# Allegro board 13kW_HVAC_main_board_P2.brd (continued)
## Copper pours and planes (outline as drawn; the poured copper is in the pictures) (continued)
DRV_W_H on BOTTOM: 111.53,22.58 111.4,22.35 111.17,22.3 110.82,22.48 110.79,22.86 111.96,25.22 112.44,25.32 113.02,26.67 112.95,26.92 111.93,28.52 108.32,30.22 105.04,31.64 105.02,31.75 105.37,32.51 105.5,32.54 107.1,31.8 108.3,31.21 108.56,31.24 110.2,30.46 110.73,30.76 111.01,30.86 111.03,30.85 113.69,29.61 115.05,29.28 115.11,29.11 115.25,28.32 113.43,24.63 113.15,24.58 112.28,24.25 112.15,23.85
G_L on TOP: 111.72,85.75 112.99,85.97 114.26,85.47 114.39,85.21 114.01,84.45 113.88,84.45 112.87,84.96 112.61,84.96 112.11,83.94 111.98,83.94 111.34,84.2 111.19,84.58
G_L on BOTTOM: 51.78,82.93 51.4,83.31 51.4,84.45 51.65,84.7 53.56,84.7 53.69,84.58 53.69,83.05 53.56,82.93
G_L on BOTTOM: 70.96,37.84 70.96,37.33 71.21,36.95 71.47,36.95 72.1,37.33 72.23,37.59 71.97,38.1 71.72,38.22
G_L on BOTTOM: 102.96,82.16 102.2,82.55 102.07,82.93 102.45,83.82 102.83,84.45 103.09,84.45 103.85,84.07 103.85,83.82 103.22,82.29
G_L on I_SAMPLING05: 53.18,92.71 56.35,92.71 56.61,92.32 56.61,82.8 56.39,82.52 51.97,82.54 51.97,82.55 51.57,82.55 51.22,82.9 51.22,84.65 50.79,85.09 46.32,85.09 45.79,85.68 45.3,88.01 45.3,98.17 45.56,98.55 46.19,98.54 49.85,98.53 50.76,97.53 50.76,92.96 51.16,92.72
G_L on I_SAMPLING05: 100.68,81.28 102.06,84.21 105.81,87.96 107.16,88.39 118.98,83.34 119.19,82.31 118.36,80.43 116.02,79.32 112.41,80.86 111.29,80.46 109.26,76.22 109.08,76.2 108.73,76.17 107.16,76.84 100.39,79.94 100.4,80.72
G_L on I_SAMPLING05: 60.93,31.89 62.21,34.42 60.92,37.46 61.43,38.48 69.9,42.44 69.94,42.41 70.32,42.29 72.35,37.97 71.31,35.92 72.55,33.1 72.44,31.89 63.75,27.68 63.06,26.41 61.66,25.73 61.25,25.9 59.58,29.54 59.63,29.66
G_U_H on I_SAMPLING05: 96.1,111.38 96.1,107.08 96.08,107.06 96.08,106.68 96.7,106.05 101.75,106.05 102.1,105.71 102.1,103.86 102.66,103.3 107,103.3 107,105.96 106.97,105.99 106.97,107.13 108.85,109.01 108.85,112.8 107.3,114.35 104.76,114.35 103.9,113.48 99.23,113.48 98.67,114.04 96.31,114.04 96.31,114.02 96.1,113.81
G_V_H on I_SAMPLING05: 32.66,75.76 30.2,74.65 29.96,73.84 31.94,69.11 31.94,68.25 31.08,67.94 30.32,67.56 27.14,66.04 25.36,65.27 24.86,65.27 24.17,66.44 22.77,69.36 22.47,69.44 22.45,69.44 21.91,70.59 20.61,70.51 20.36,71.04 20.36,72.27 19.47,74.29 19.46,74.84 28.3,79 28.97,79.02 29.5,79.02 31.28,79.78 31.71,79.57 32.65,77.44 33.37,77.34 33.67,76.58 33.57,76.12
G_W_H on I_SAMPLING05: 106.16,33.71 108.77,32.52 109.03,32.39 109.45,32.57 109.54,32.61 113.22,30.96 115.15,26.36 113.18,21.92 110.12,21.26 106.87,22.68 106.72,23.69 103.85,25.04 103.7,25.95 104.69,28.09 103.09,31.67 103.19,31.97 104.03,33.8 105.02,34.03 106.16,33.71
IPH_U- on TOP: 66.66,63.16 66.65,77.2 60.54,83.31 60.54,86.48 61.05,86.99 63.85,86.99 67.91,82.93 74.77,82.93 75.15,82.55 75.15,79.37 74.74,78.96 74.74,77.95 74.76,47.24 74.76,46.54 73.02,44.8 73.02,37.21 78.96,31.27 78.96,31.21 80.65,27.31 80.65,19.93 73.72,9.73 69.6,6.6 44.8,6.6 44.16,7.23 44.16,16.38 44.92,17.14 66.13,17.14 70.96,21.97 70.96,24.88 69.43,28.06 67.53,31.11 65.55,35.82 65.62,42.97 63.69,46.3 63.52,47.85 63.58,48.13 62.07,57.53 62.07,57.91 62.32,58.29 63.97,59.69 66.13,61.21
IPH_U- on TOP: 92.29,63.75 89.12,65.27 89.12,66.18 93.31,74.8 96.36,75.94 96.87,76.2 101.82,73.91 101.95,72.89 101.06,70.99 95.64,68.96 95.63,68.94 93.18,63.75 92.8,63.5
IPH_U- on BOTTOM: 60.54,83.82 65.12,79.24 79.97,79.24 80.1,79.37 80.1,90.55 79.97,90.67 77.82,90.67 77.31,90.17 77.31,82.93 76.98,82.6 75.55,82.6 75.38,82.77 67.3,82.77 65.24,84.83 65.24,85.59 63.85,86.99 61.05,86.99 60.54,86.48
IPH_U- on BOTTOM: 52.67,59.05 52.67,59.24 54.19,59.94 62.84,63.96 62.86,63.94 64.1,64.38 64.61,64.26 71.34,49.65 70.58,47.24 66.28,45.33 65.24,45.28 64.5,45.48 63.92,45.91 63.59,46.48 63.46,47.11 63.46,47.62 64.86,51.56 61.81,58.16 61.56,58.9 60.47,59.79 59.55,59.68 59.53,59.69 53.69,57.27 53.3,57.4
IPH_U- on BOTTOM: 66.08,3.84 65.75,3.5 56.95,3.5 53.94,6.51 45.4,6.51 43.97,7.94 43.97,16.28 44.57,16.87 51.91,16.87 51.95,16.83 53.05,16.83 54.39,15.49 65.57,15.49 66.08,14.98
IPH_U- on BOTTOM: 96.93,69.46 100.9,70.75 101.31,71.06 101.73,71.54 101.99,72.15 101.97,72.87 101.68,73.58 101,74.38 99.3,75.3 96.62,76.37 95.2,76.37 92.97,74.15 92.95,74.1 89.96,67.55 89.66,66.9 89.45,66.41 88.73,64.53 86.93,60.65 87.04,60.13 87.04,60.12 87.22,59.31 96.76,54.86 97.68,54.71 97.81,54.81 97.82,54.82 98.64,56.36 98.59,56.77 98.34,57.15 92.34,60.09 92.34,60.1 91.56,61.08 91.56,61.62 95.49,69.19
IPH_U- on VCC02: 92.29,63.75 89.12,65.27 89.12,66.18 91.84,71.78 96.47,76 96.87,76.2 101.82,73.91 101.95,72.89 101.06,70.99 95.64,68.96 95.63,68.94 93.18,63.75 92.8,63.5
IPH_U- on VCC02: 60.29,86.61 60.29,81.91 61.05,81.15 74.89,81.15 75.28,81.53 75.28,84.07 75.02,84.32 67.15,84.32 64.48,86.99 60.67,86.99
IPH_U- on VCC02: 65.85,44.37 65.19,44.52 63.34,47.98 64.28,51.05 61.46,57.32 61.74,57.86 64,58.92 64.4,58.77 67.6,51.58 69.87,46.78 69.59,46.12
IPH_U- on GND03: 92.29,63.75 89.81,64.94 89.48,66.93 93.31,74.8 96.36,75.94 96.87,76.2 101.82,73.91 101.95,72.89 101.06,70.99 95.64,68.96 95.63,68.94 93.18,63.75 92.8,63.5
IPH_U- on GND03: 65.85,44.37 65.19,44.52 63.34,47.98 64.28,51.05 61.46,57.32 61.74,57.86 63.72,58.79 64.1,58.67 69.75,46.51 69.59,46.12
IPH_U- on GND03: 67.27,82.42 67.27,81.4 67.53,81.15 75.15,81.15 75.4,81.4 75.4,82.29 75.02,82.67 67.53,82.67
IPH_U- on PWM04: 78.73,78.53 79.94,78.53 98.06,75.65 101.21,74.32 101.82,73.15 101.77,72.21 101.08,70.96 98.16,70.38 97.49,70.32 90.13,62.23 86.83,61.08 66.47,45.43 65.18,45.35 64.15,45.84 63.61,46.77 63.59,47.5 63.77,48.18 63.65,53.84 61.94,57.4 63.45,63.62 63.39,66.48 63.29,67.13 60.69,84.4 60.8,85.9 61.36,86.58 62.04,86.89 64.32,86.89 68.5,82.72 69.45,82.72 69.51,82.69 74.88,82.69 75.28,82.29 75.28,81.42 78.47,78.65
IPH_U- on I_SAMPLING05: 42.83,6.41 41.67,7.56 41.67,16.2 42.75,17.28 50.18,17.28 51.89,15.57 63.52,15.57 71.26,23.31 73.4,32.1 73.34,39.47 70.78,43.56 64.63,45.51 64.07,45.94 63.24,47.72 63.36,48.81 62.61,56.01 61.94,57.91 62.18,60.21 60.27,78.58 60.18,83.87 60.64,86.37 62.09,86.99 63.39,86.97 66,85.09 70.49,83.65 83.51,80.6 97.11,77.52 100.84,75.75 101.44,74.9 101.72,73.86 101.79,72.13 101.33,71.33 100.27,70.72 96.99,70.71 87.89,58.82 81.52,48.07 81.51,46.79 81.55,46.68 81.55,19.63 75.58,13.66 75.58,8.07 73.8,5.91 44.04,5.91
NETC7_1 on TOP: 84.04,94.1 84.79,94.62 100.85,94.64 101.24,94.22 104.29,94.23 104.61,93.98 104.61,92.07 104.4,91.86 103.42,91.84 93.92,82.16 84.29,82.16 84.04,82.42
NETC7_1 on TOP: 45.1,79.84 45.35,79.43 47.01,76.16 51.8,73.74 53.46,74.51 56.2,72.88 57.41,70.13 57.24,68.32 47.84,63.37 47.44,63.37 41.33,76.63 40.76,76.92 40.26,78.22 40.32,78.53 40.36,78.73 43.91,80.38
NETC7_1 on TOP: 84.99,45.78 84.29,45.08 83.02,42.41 82.9,42.41 80.99,43.3 80.86,43.43 81.24,44.32 79.97,47.24 79.21,47.24 78.83,47.62 78.82,47.62 78.82,47.75 78.82,48.13 78.7,77.72 79.21,78.35 82.51,78.35 83.78,77.08 83.78,62.57 83.81,62.52 85.56,56.89 90.64,54.48 98.39,50.16 98.55,48.74 98.38,48.39 98.39,48.38 96.1,43.56 95.92,43.21 95.62,43.13 92.36,44.64 90.17,45.71 87.35,45.71 87.28,45.78
NETC7_1 on BOTTOM: 70.58,3.04 70.07,3.55 70.07,15.62 74.39,19.93 77.55,29.53 77.82,30.09 77.84,32.01 78.9,37.15 81.54,46.97 85.62,55.97 85.94,55.97 85.94,55.98 98.54,50.21 98.75,49.77 90.57,32.58 89.09,31.04 89.02,21.35 89.03,21.34 89.03,17.63 92.86,13.8 92.86,4.92 91.71,3.76 88.92,3.76 88.2,3.04
NETC7_1 on BOTTOM: 84.42,94.48 100.8,94.48 101.19,94.33 101.31,94.23 101.31,91.94 100.56,91.07 99.1,91.14 86.77,78.81 84.22,78.81 84.17,78.86 84.17,94.23
NETC7_1 on BOTTOM: 60.36,68.43 60.82,67.52 51.53,63.24 49.58,62.27 48.1,62.61 47.84,62.84 46.95,64.77 40.48,78.61 44.16,80.39 44.54,80.13 45.94,77.47 54.07,74.04 55.31,73.35
NETC7_1 on VCC02: 70.7,2.92 70.07,3.55 70.07,17.65 74.39,21.97 74.46,35.43 77.69,38.65 77.69,44.57 70.36,51.9 67.15,59.05 66.26,60.83 66.25,60.83 63.59,66.29 61.18,67.56 50.26,62.35 47.55,62.84 47.53,62.88 47.53,62.88 40.64,77.66 41,78.66 42.09,79.17 43.99,80.06 44.18,80.14 47.65,78.76 48.4,78.49 50.74,73.48 50.87,73.37 64.23,78.74 75.91,78.74 78.7,81.53 78.7,89.92 83.5,94.71 101.21,94.71 101.74,94.18 101.74,90.98 99.79,89.02 99.79,82.93 97.82,80.96 96.48,80.92 95.27,79.4 95.34,78.48 87.98,71.12 84.04,61.97 85.31,58.54 86.32,56.64 91.79,54.1 98.26,50.8 98.79,50.27 92.42,36.73 91.91,35.68 91.91,14.43 92.93,13.42 92.93,4.82 91.98,3.87 88.12,2.92
NETC7_1 on GND03: 92.29,37.59 92.03,37.73 72.57,47.09 71.9,48.29 65.88,60.96 64.85,60.98 60.04,61.27 55.38,59.08 49.72,61.11 48.17,61.57 47.53,62.88 47.53,62.88 40.64,77.66 41,78.66 42.09,79.17 43.99,80.06 44.18,80.14 44.88,79.86 44.88,79.85 46.24,76.99 49.3,76.57 50.6,73.78 52.64,73.78 54.39,74.34 54.66,74.47 54.7,74.44 57.22,75.25 57.37,75.3 65.12,78.8 75.91,78.8 78.7,81.59 78.7,89.94 78.73,89.94 83.48,94.69 101.3,94.69 101.77,94.21 101.74,94.18 101.74,90.37 98.21,86.84 89.8,78.46 85.77,69.97 85.87,67 87.42,61.84 87.98,61.65 90.64,60.38 98.45,56.75 99.84,52.55 93.04,38.1 92.93,37.84
NETC7_1 on PWM04: 42.09,79.17 43.99,80.06 44.18,80.14 44.88,79.86 44.88,79.85 46.24,76.99 49.3,76.57 50.81,73.33 50.91,73.3 51.87,73.17 54.66,74.47 56.01,73.68 59.26,66.74 59.02,66.42 50.13,62.35 49.1,62.31 47.53,62.88 47.53,62.88 40.64,77.66 41,78.66
NETC7_1 on PWM04: 101.61,92.99 101.61,90.89 101.6,90.68 98.89,88.12 98.32,87.55 92.63,87.55 92.56,87.47 92.04,86.66 92.04,83.58 92.04,81.98 91.3,81.25 81.93,81.25 81.12,82.06 81.12,83.94 81.09,91.72 83.19,93.57 84.55,94.93 84.55,94.94 100.85,94.94 101.61,94.19
NETC7_1 on I_SAMPLING05: 42.09,79.17 43.99,80.06 44.18,80.14 47.65,78.76 48.4,78.49 50.81,73.33 50.91,73.3 51.87,73.17 53.69,74.02 54.45,73.91 57.07,68.75 57.09,66.87 48.35,62.86 47.33,63.31 40.64,77.66 41,78.66
NETC7_1 on I_SAMPLING05: 101.61,92.99 101.61,90.89 101.6,90.68 98.89,88.12 98.32,87.55 92.63,87.55 92.56,87.47 92.04,86.66 92.04,83.58 90.75,82.69 83.67,82.68 81.12,83.99 81.09,91.72 83.19,93.57 84.55,94.93 84.55,94.94 100.85,94.94 101.61,94.19
NETC19_1 on BOTTOM (solid shape): 25.1,49.61 26.69,46.2 26.56,45.86 24.61,44.95 24.27,45.07 23.84,46 23.5,46.12 22.83,46.24 20.76,45.27 20.59,45.33 20.27,46.02 20.33,46.19 21.14,46.57 21.38,47.23 21.43,47.25 21,48.18 20.96,48.15 20.8,48.5 20.84,48.52 20.41,49.44 20.37,49.42 20.21,49.77 20.25,49.79 19.96,50.42 20.06,50.69 20.97,51.11
NETC20_1 on BOTTOM: 79.98,124.25 79.98,126.54 80.11,126.66 80.87,126.66 81,126.54 81,125.65 81.51,125.14 84.94,125.14 85.19,124.89 85.19,123.88 82.08,120.77 78.32,120.77 78.07,121.03 78.07,123.19 78.32,123.44 79.34,123.44 79.59,123.69
NETC32_1 on BOTTOM (solid shape): 127.64,43.37 127.77,43.03 127.34,42.11 127.46,41.78 127.8,41.19 128.95,40.65 128.93,40.61 129.89,40.16 129.93,40.05 129.61,39.37 129.46,39.31 129.44,39.3 129.03,39.49 128.23,39.49 127.22,37.46 126.76,37.23 126.58,37.32 124.3,41.9 125.35,44.16 125.69,44.28
NETC60_2 on TOP: 123.92,104.14 128.36,106.17 128.74,105.41 124.3,103.37
NETC65_1 on TOP: 118.48,110.17 118.46,109.98 118.46,109.85 118.71,109.34 118.71,109.35 119.01,109.49 119.02,109.56 118.9,109.84 118.99,110.86 118.85,111.15 118.61,111.64 118.41,112.02 118.35,112.04 117.71,111.75 117.92,111.32 118.27,110.58
NETCON3_1 on TOP, BOTTOM: 48.19,29.3 47.79,28.22 40.72,24.92 39.7,25.29 36.06,33.11 38.02,38.5 36.74,41.23 36.73,41.24 36.52,41.68 36.56,41.78 38.7,42.78 38.71,42.81 38.6,43.04 36.51,42.06 36.31,42.14 34.5,46.01 34.55,46.17 37.59,47.61 38,47.54 39.48,46.03 42.04,40.55 43.11,40.16 44.65,36.86 44.66,36.85 47.74,30.24 47.75,30.23
NETCON3_1 on VCC02: 48.22,29.29 47.82,28.21 43.87,26.36 40.1,26.36 38.47,27.99 36.09,33.09 38.05,38.48 36.78,41.22 36.76,41.22 36.55,41.66 36.59,41.76 38.73,42.76 38.74,42.8 38.64,43.03 36.54,42.05 36.34,42.12 34.54,45.99 34.6,46.22 37.78,47.68 38.63,48.07 39.62,47.71 40.16,46.55 40.16,46.54 44.68,36.84 44.69,36.84 47.77,30.22 47.78,30.22
NETCON3_1 on GND03: 48.23,29.29 47.84,28.21 40.76,24.91 39.75,25.28 36.1,33.1 38.06,38.49 36.79,41.22 36.77,41.23 36.57,41.67 36.6,41.77 38.74,42.77 38.76,42.8 38.65,43.03 36.55,42.05 36.35,42.13 34.55,45.99 34.61,46.22 37.8,47.68 38.65,48.08 39.63,47.72 40.18,46.55 40.17,46.54 44.69,36.85 44.7,36.84 47.79,30.22 47.8,30.22
NETCON3_1 on PWM04: 48.21,29.29 47.81,28.21 40.74,24.91 39.72,25.28 36.08,33.1 38.04,38.49 36.76,41.22 36.75,41.23 36.54,41.67 36.58,41.77 38.72,42.77 38.73,42.8 38.62,43.03 36.53,42.05 36.33,42.13 34.52,45.99 34.59,46.22 37.77,47.68 38.62,48.08 39.6,47.72 40.15,46.55 40.15,46.54 44.67,36.85 44.68,36.84 47.76,30.22 47.77,30.22
NETCON3_1 on I_SAMPLING05: 48.21,29.32 47.81,28.24 40.74,24.94 39.72,25.31 36.08,33.12 38.04,38.51 36.76,41.25 36.75,41.25 36.54,41.69 36.58,41.79 38.72,42.79 38.73,42.82 38.62,43.05 36.53,42.08 36.33,42.15 34.52,46.02 34.59,46.24 37.77,47.7 38.62,48.1 39.6,47.74 40.15,46.57 40.15,46.57 44.67,36.87 44.68,36.87 47.76,30.25 47.77,30.24
NETCON4_1 on TOP, BOTTOM: 124.44,71.53 125.52,71.93 132.6,68.63 132.97,67.61 129.32,59.8 123.93,57.83 122.66,55.1 122.66,55.08 122.46,54.64 122.36,54.61 120.22,55.6 120.18,55.59 120.08,55.36 122.17,54.39 122.24,54.18 120.44,50.32 120.29,50.25 117.22,51.65 117.02,52.01 117.22,54.11 119.78,59.59 119.39,60.67 120.93,63.97 120.93,63.98 124.01,70.59 124.01,70.6
NETCON4_1 on VCC02: 124.44,71.51 125.52,71.9 132.6,68.6 132.97,67.59 129.32,59.77 123.93,57.81 122.66,55.08 122.66,55.06 122.46,54.62 122.36,54.58 120.22,55.58 120.18,55.57 120.08,55.34 122.17,54.36 122.24,54.16 120.44,50.29 120.23,50.19 117.06,51.7 116.21,52.09 115.85,53.07 116.4,54.24 116.41,54.25 120.93,63.94 120.93,63.95 124.01,70.57 124.01,70.58
NETCON4_1 on GND03: 124.46,71.48 125.54,71.88 132.61,68.58 132.98,67.56 129.34,59.75 123.95,57.79 122.67,55.05 122.68,55.03 122.47,54.59 122.37,54.56 120.23,55.56 120.2,55.54 120.09,55.31 122.19,54.34 122.26,54.13 120.46,50.27 120.24,50.17 117.08,51.67 116.23,52.07 115.87,53.05 116.41,54.22 116.42,54.22 117.36,56.24 120.94,63.92 120.94,63.93 124.03,70.55 124.02,70.56
NETCON4_1 on PWM04: 124.45,71.49 125.53,71.89 132.6,68.59 132.97,67.57 129.33,59.75 123.94,57.79 122.67,55.06 122.67,55.04 122.47,54.6 122.37,54.57 120.23,55.56 120.19,55.55 120.08,55.32 122.18,54.35 122.25,54.14 120.45,50.28 120.24,50.18 117.07,51.68 116.22,52.08 115.86,53.06 116.41,54.23 116.42,54.23 117.36,56.25 120.94,63.92 120.94,63.94 124.02,70.55 124.02,70.56
NETCON4_1 on I_SAMPLING05: 124.45,71.52 125.53,71.92 132.61,68.62 132.98,67.6 129.33,59.79 123.95,57.82 122.67,55.09 122.68,55.07 122.47,54.63 122.37,54.6 120.23,55.6 120.2,55.58 120.09,55.35 122.18,54.38 122.26,54.17 120.45,50.31 120.24,50.21 117.07,51.71 116.22,52.11 115.87,53.09 116.41,54.26 116.42,54.26 117.36,56.28 120.94,63.96 120.94,63.97 124.02,70.59 124.02,70.6
NETCON5_1 on TOP: 74.84,113.91 74.97,113.8 74.99,110.43 74.75,110.1 72.76,109.39 66.72,109.39 65.91,108.59 62.27,108.59 62.26,108.58 54.96,108.58 54.95,108.57 53.92,108.57 53.11,109.39 53.11,116.33 53.79,117.01 54.19,117.19 54.96,117.19 55.45,116.95 55.56,116.84 60.95,116.84 61.31,117.19 62.19,117.19 62.43,117.07 62.93,116.58 63.08,116.45 63.08,113.79 64.35,112.52 65.37,112.52 65.37,112.58 68.23,112.6 69.02,112.6 69.2,112.78 69.2,113.59 69.52,113.92 69.58,113.92 69.59,113.91 70.07,113.91 70.14,113.84 70.14,111.48 70.17,111.45 70.42,111.45 70.42,113.76 70.58,113.91
NETCON5_1 on BOTTOM: 53.92,108.57 53.11,109.39 53.11,117.19 53.88,117.96 62.5,117.96 66.55,113.9 69.57,113.9 69.59,113.91 70.07,113.91 70.14,113.84 70.14,111.48 70.17,111.45 70.42,111.45 70.42,113.76 70.58,113.91 74.84,113.91 74.97,113.8 74.99,110.43 74.75,110.1 72.76,109.39 66.72,109.39 65.91,108.59 62.27,108.59 62.26,108.58 54.96,108.58 54.95,108.57
NETCON5_1 on VCC02: 53.95,108.4 53.13,109.22 53.13,117.02 53.9,117.79 62.52,117.79 66.58,113.73 69.59,113.73 69.61,113.74 70.09,113.74 70.17,113.67 70.17,111.31 70.19,111.28 70.45,111.28 70.45,113.59 70.6,113.74 74.87,113.74 75.05,113.59 75.02,110.09 75.02,109.15 74.28,108.41 72.99,108.41 72.99,108.42 62.29,108.42 62.28,108.41 54.98,108.41 54.97,108.4
NETCON5_1 on GND03: 53.93,108.42 53.12,109.24 53.12,115.77 55.15,117.81 62.51,117.81 66.56,113.75 69.58,113.75 69.6,113.77 70.08,113.77 70.15,113.69 70.15,111.33 70.18,111.3 70.43,111.3 70.43,113.61 70.59,113.77 74.85,113.77 75.03,113.61 75.01,110.11 75.01,109.17 74.27,108.43 72.98,108.43 72.97,108.44 62.28,108.44 62.27,108.43 54.96,108.43 54.96,108.42
NETCON5_1 on PWM04: 53.91,108.42 53.09,109.24 53.09,117.04 53.86,117.81 62.48,117.81 66.54,113.75 69.55,113.75 69.57,113.77 70.05,113.77 70.13,113.69 70.13,111.33 70.15,111.3 70.41,111.3 70.41,113.61 70.56,113.77 74.83,113.77 75.01,113.61 74.98,110.11 74.98,109.17 74.24,108.43 72.95,108.43 72.95,108.44 62.25,108.44 62.24,108.43 54.94,108.43 54.93,108.42
NETCON5_1 on I_SAMPLING05: 53.9,108.5 53.09,109.31 53.09,116.33 54.4,117.64 62.71,117.64 66.53,113.83 69.55,113.83 69.56,113.84 70.04,113.84 70.12,113.76 70.12,111.4 70.14,111.37 70.4,111.37 70.4,113.69 70.55,113.84 74.82,113.84 75,113.69 74.97,110.18 74.97,109.24 74.23,108.5 72.94,108.5 72.94,108.51 62.24,108.51 62.23,108.5 54.93,108.5 54.92,108.5
NETPAD8_1 on TOP: 54.01,28.81 53.89,28.48 50.32,26.81 49.98,26.94 43.5,40.84 42.47,41.21 40.08,46.31 38.36,48.15 37.61,48.29 37.43,48.21 34.32,46.76 34.15,46.82 32.37,50.64 32.43,50.81 34.36,51.71 34.41,51.62 34.64,51.73 28.2,65.54 32.99,67.71 33.42,67.56 39.76,53.98 40.49,50.37 42.38,47.92 44.87,46.67 45.77,46.49
NETPAD8_1 on BOTTOM: 54.01,28.81 53.89,28.48 50.32,26.81 49.98,26.94 43.5,40.84 42.47,41.21 40.08,46.31 38.36,48.15 37.61,48.29 37.43,48.21 34.32,46.76 34.15,46.82 32.37,50.64 32.43,50.81 34.36,51.71 34.41,51.62 34.64,51.73 28.2,65.54 28.38,66.05 32.41,67.93 33.42,67.56 39.76,53.98 40.49,50.37 42.38,47.92 44.87,46.67 45.77,46.49
NETPAD8_1 on VCC02: 54.02,28.79 53.9,28.45 50.33,26.79 49.99,26.91 43.37,41.11 43.35,41.12 42.67,42.57 42.68,42.59 39.98,48.39 38.79,48.82 34.33,46.73 34.16,46.8 32.38,50.62 32.44,50.79 34.37,51.69 34.42,51.6 34.65,51.7 28.21,65.51 28.39,66.02 32.42,67.9 33.43,67.53 38.3,57.08 39.15,55.26 42.19,54.16 45.43,47.2
NETPAD8_1 on GND03: 54.03,28.79 53.91,28.45 50.34,26.79 50,26.91 43.38,41.12 43.36,41.12 42.69,42.57 42.69,42.59 39.99,48.39 38.81,48.82 34.34,46.74 34.17,46.8 32.39,50.62 32.45,50.79 34.39,51.69 34.43,51.6 34.66,51.71 28.22,65.52 28.4,66.02 32.43,67.9 33.44,67.53 38.32,57.08 39.17,55.27 42.2,54.16 45.45,47.21
NETPAD8_1 on PWM04: 54.01,28.79 53.88,28.45 50.32,26.79 49.98,26.91 43.36,41.12 43.34,41.12 42.66,42.57 42.67,42.59 39.96,48.39 38.78,48.82 34.32,46.74 34.15,46.8 32.37,50.62 32.43,50.79 34.36,51.69 34.4,51.6 34.63,51.71 28.19,65.52 28.38,66.02 32.41,67.9 33.42,67.53 38.29,57.08 39.14,55.27 42.18,54.16 45.42,47.21
NETPAD8_1 on I_SAMPLING05: 54.01,28.82 53.88,28.48 50.32,26.82 49.98,26.94 43.36,41.14 43.34,41.15 42.66,42.6 42.67,42.61 39.96,48.42 38.78,48.85 34.32,46.76 34.15,46.82 32.37,50.65 32.43,50.81 34.36,51.72 34.4,51.62 34.63,51.73 28.19,65.54 28.38,66.05 32.41,67.93 33.42,67.56 38.29,57.11 39.14,55.29 42.18,54.18 45.42,47.23
NETPAD10_1 on TOP: 121.07,76.31 121.41,76.43 124.98,74.77 125.1,74.43 118.62,60.53 118.99,59.5 116.62,54.39 116.32,51.89 116.69,51.23 116.87,51.14 119.98,49.69 120.04,49.52 118.26,45.7 118.09,45.64 116.16,46.54 116.2,46.63 115.97,46.74 110,33.93 109.15,33.69 105.17,35.53 104.96,36.35 110.96,49.22 113.26,52.1 113.91,55.13 113.27,57.84 112.83,58.63
NETPAD10_1 on BOTTOM: 121.07,76.31 121.41,76.43 124.98,74.77 125.1,74.43 118.62,60.53 118.99,59.5 116.62,54.39 116.32,51.89 116.69,51.23 116.87,51.14 119.98,49.69 120.04,49.52 118.26,45.7 118.09,45.64 116.16,46.54 116.2,46.63 115.97,46.74 109.53,32.93 109.02,32.74 104.99,34.62 104.63,35.63 110.96,49.22 113.26,52.1 113.91,55.13 113.27,57.84 112.83,58.63
NETPAD10_1 on VCC02: 121.1,76.27 121.43,76.4 125,74.73 125.12,74.4 118.5,60.19 118.51,60.18 117.83,58.73 117.81,58.72 115.11,52.92 115.54,51.74 120,49.65 120.07,49.49 118.28,45.66 118.12,45.6 116.18,46.5 116.22,46.6 115.99,46.7 109.55,32.89 109.05,32.71 105.02,34.59 104.65,35.6 109.52,46.05 110.37,47.87 109.27,50.91
NETPAD10_1 on GND03: 121.11,76.25 121.45,76.37 125.02,74.71 125.14,74.37 118.51,60.17 118.52,60.15 117.84,58.7 117.83,58.69 115.12,52.89 115.55,51.71 120.02,49.63 120.08,49.46 118.3,45.64 118.13,45.58 116.2,46.48 116.24,46.57 116.01,46.68 109.57,32.87 109.06,32.68 105.03,34.56 104.66,35.57 109.54,46.03 110.39,47.84 109.28,50.88
NETPAD10_1 on PWM04: 121.1,76.26 121.44,76.38 125.01,74.72 125.13,74.38 118.51,60.18 118.52,60.16 117.84,58.71 117.82,58.7 115.12,52.9 115.55,51.72 120.01,49.64 120.07,49.47 118.29,45.65 118.12,45.59 116.19,46.49 116.23,46.58 116,46.69 109.56,32.88 109.06,32.69 105.03,34.57 104.66,35.58 109.53,46.03 110.38,47.85 109.27,50.89
NETPAD10_1 on I_SAMPLING05: 121.11,76.29 121.44,76.41 125.01,74.75 125.14,74.41 118.51,60.21 118.52,60.19 117.84,58.74 117.83,58.73 115.12,52.93 115.55,51.75 120.02,49.67 120.08,49.5 118.3,45.68 118.13,45.62 116.19,46.52 116.24,46.61 116.01,46.72 109.57,32.91 109.06,32.72 105.03,34.6 104.66,35.61 109.54,46.06 110.38,47.88 109.28,50.92
NETPAD11_1 on TOP, BOTTOM: 51.02,103.5 50.76,103.75 50.76,107.69 51.02,107.95 66.36,107.95 67.13,108.72 72.76,108.73 75.16,109.51 75.6,110.13 75.61,110.33 75.61,113.76 75.73,113.89 79.95,113.89 80.08,113.76 80.08,111.63 79.97,111.63 79.97,111.37 95.21,111.37 95.6,110.99 95.6,106.55 94.83,105.79 79.85,105.79 76.27,106.65 73.24,105.96 71.06,104.24 70.53,103.5
NETPAD11_1 on VCC02: 51.04,103.36 50.79,103.61 50.79,107.55 51.04,107.8 66.71,107.8 66.73,107.81 68.33,107.81 68.34,107.8 74.74,107.8 75.63,108.69 75.63,113.62 75.76,113.74 79.97,113.74 80.1,113.62 80.1,111.48 80,111.48 80,111.23 95.24,111.23 95.62,110.85 95.62,106.4 94.86,105.64 81.32,105.64 79.03,103.36
NETPAD11_1 on GND03: 51.03,103.38 50.77,103.63 50.77,107.57 51.03,107.82 66.7,107.82 66.71,107.83 68.31,107.83 68.33,107.82 74.73,107.82 75.61,108.71 75.61,113.64 75.74,113.77 79.96,113.77 80.09,113.64 80.09,111.51 79.98,111.51 79.98,111.25 95.22,111.25 95.6,110.87 95.6,106.43 94.84,105.66 81.3,105.66 79.02,103.38
NETPAD11_1 on PWM04: 51,103.38 50.75,103.63 50.75,107.57 51,107.82 66.67,107.82 66.69,107.83 68.29,107.83 68.3,107.82 74.7,107.82 75.59,108.71 75.59,113.64 75.72,113.77 79.93,113.77 80.06,113.64 80.06,111.51 79.96,111.51 79.96,111.25 95.2,111.25 95.58,110.87 95.58,106.43 94.82,105.66 81.28,105.66 78.99,103.38
NETPAD11_1 on I_SAMPLING05: 50.99,103.45 50.74,103.7 50.74,107.64 50.99,107.89 66.66,107.89 66.68,107.91 68.28,107.91 68.29,107.89 74.69,107.89 75.58,108.78 75.58,113.71 75.71,113.84 79.92,113.84 80.05,113.71 80.05,111.58 79.95,111.58 79.95,111.32 95.19,111.32 95.57,110.94 95.57,106.5 94.81,105.74 81.27,105.74 78.98,103.45
NETPAD21_1 on TOP, BOTTOM, VCC02, GND03, PWM04, I_SAMPLING05: 108.04,75.93 104.05,77.59 103.71,77.45 102.5,74.52 102.96,72.94 102.07,70.66 101.06,69.9 98.45,68.9 96.55,65.13 95.41,62.39 96.92,61.54 99,60.8 104.04,63.98 108.52,74.77
NETPAD23_1 on TOP (solid shape): 74.16,88.11 74.26,86.89 74.3,85.5 74.26,85.47 67.02,85.47 65.12,87.37 60.89,87.37 57.11,87.37 56.86,87.63 56.86,91.94 57.75,92.83 69.43,92.83
NETPAD23_1 on BOTTOM: 56.86,91.94 56.86,87.63 57.11,87.37 65.12,87.37 65.84,86.65 65.85,86.66 74.13,86.66 74.26,86.79 74.26,88.01 69.43,92.83 57.75,92.83
NETPAD23_1 on VCC02, GND03, PWM04, I_SAMPLING05: 56.86,91.94 56.86,87.63 57.11,87.37 65.12,87.37 67.02,85.47 74.26,85.47 74.3,85.5 74.26,86.89 74.16,88.11 69.43,92.83 57.75,92.83
NETPAD24_1 on TOP, BOTTOM, VCC02, GND03, PWM04, I_SAMPLING05: 62.38,39.21 65.21,40.69 65.24,41.02 59.73,53.95 58.62,56 58.03,55.98 55.51,54.76 55.78,51.82 61,39.94 61.18,39.59
VA+3.3V on BOTTOM: 40.74,107.69 40.73,107.88 41.62,109.22 41.62,109.47 41.5,110.17 43.14,112.52 43.02,113.79 41.62,114.8 41.59,114.8 40.73,114.55 39.84,113.28 39.59,113.15 38.45,114.04 38.45,114.17 39.69,116.07 38.22,117.55 38.22,121.03 40.43,123.24 48.78,123.24 50,124.46 50.13,124.46 50.87,125.19 58.82,125.19 58.89,125.12 58.89,123.8 58.82,123.72 51.78,123.72 49.98,121.92 41.59,121.92 39.97,120.29 39.97,119.35 44.16,115.16 44.16,114.55 44.03,114.04 44.67,111.63 43.02,108.2 42.11,106.95 41.89,106.95
VA+3.3V on I_SAMPLING05: 39.57,113.11 39.51,113.14 38.38,113.96 38.38,114.11 39.59,116.02 40.33,118.49 40.59,118.74 41.24,118.74 43.14,117.22 43.16,117.2 43.16,116.56 40.91,114.77 39.79,113.14
VA+5V on BOTTOM: 30,109.16 28.8,109.29 26.5,111.04 26.46,111.57 27.44,112.86 27.69,113.04 28.88,112.92 30.99,112.35 32.58,112.66 35.69,116.78 36.79,117.32 37.82,117.27 39.01,116.32 39.03,116.11 37.82,114.44 37.08,114.46 37.01,114.35 36.49,113.59 36.41,113.05 35.33,111.52 35.43,110.48 34.7,109.47 33.69,109.56 32.31,110.35 31.84,110.51 31.13,110.45

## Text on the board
User.Comments: CR_1_3 | CR_2_1 | CR_1_1 | CR_U5_1 | CR_22_1 | CR_T3_4 | CR_U9_1 | CR_UNNAMED_4 | CR_UNNAMED_1 | CR_UNNAMED_2 | CR_UNNAMED_7 | CR_UNNAMED_6 | CR_1_2 | CR_2_2 | CR_T3_3 | CR_UNNAMED_3
Ref Des/Silkscreen Top: 13KW_HVAC_MAIN_BOARD_P2 | 230711 | VAUX | V | VIN | U | W
User.22: FIGURE | SIZE | 10.0 | 12.0 | 32.0 | 40.0 | 47.0 | 73.0 | 122.0 | 236.0 | DRILL CHART: TOP to BOTTOM | ALL UNITS ARE IN MILS | TOLERANCE | +0.0/-0.0 | +3.0/-3.0 | PLATED | NON-PLATED | QTY | 1559 | 1 | 4 | 44 | 15 | 10 | 20 | 3
